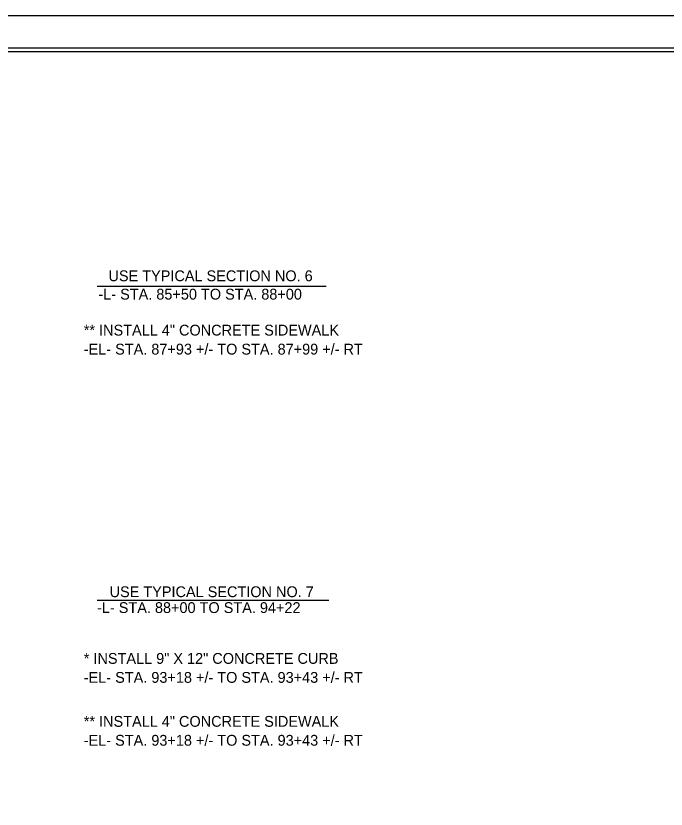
# Model space of a CAD drawing. Extents: x 1022283 to 1026986, y 174822 to 180471.
# Drawn here: x 1024733 to 1025859, y 176197 to 177572 of the extents above; entities that cross this region are included whole.
import ezdxf

# ---------------------------------------------------------------- set-up
doc = ezdxf.new("R2010")
doc.units = 0
for name, color, linetype in [('Prop Dimension', 7, 'Continuous'), ('Sheet Cutting Line CELL', 7, 'Continuous'), ('Sheet Plot Border Inside CELL', 7, 'Continuous'), ('Sheet Plot Border Outside CELL', 7, 'Continuous'), ('Sheet Typical CELL', 7, 'Continuous'), ('Typical Text Label CELL', 7, 'Continuous')]:
    doc.layers.add(name, color=color, linetype=linetype)

msp = doc.modelspace()

# ---------------------------------------------------------------- linework, layer by layer
at = {"layer": 'Sheet Cutting Line CELL'}
msp.add_line((1026493.2, 177572.5), (1022283.2, 177572.5), dxfattribs=at)
at = {"layer": 'Sheet Plot Border Inside CELL'}
msp.add_lwpolyline([(1026482, 177516.3), (1022315.7, 177516.3), (1022315.7, 174878.6), (1026482, 174878.6)], close=True, dxfattribs=at)
at = {"layer": 'Sheet Plot Border Outside CELL'}
msp.add_lwpolyline([(1026493.2, 177572.5), (1022283.2, 177572.5), (1022283.2, 174822.5), (1026493.2, 174822.5)], close=True, dxfattribs=at)
at = {"layer": 'Sheet Typical CELL'}
msp.add_lwpolyline([(1026450.7, 177510), (1022700.7, 177510), (1022700.7, 174885), (1026450.7, 174885)], close=True, dxfattribs=at)
at = {"layer": 'Typical Text Label CELL'}
for p, q in [((1024873.5, 177104), (1025270.1, 177104)), ((1024873.5, 176559.4), (1025275, 176559.4))]:
    msp.add_line(p, q, dxfattribs=at)

# ---------------------------------------------------------------- texts
at = {"layer": 'Prop Dimension'}
for s, p in [('-L- STA. 85+50 TO STA. 88+00', (1024875.6, 177080.7)), ('** INSTALL 4" CONCRETE SIDEWALK ', (1024850.2, 177018.3)), ('-EL- STA. 87+93 +/- TO STA. 87+99 +/- RT', (1024850.2, 176985.4)), ('-L- STA. 88+00 TO STA. 94+22', (1024873.2, 176537.4)), ('* INSTALL 9" X 12" CONCRETE CURB ', (1024850.2, 176449.3)), ('-EL- STA. 93+18 +/- TO STA. 93+43 +/- RT', (1024850.2, 176416.4)), ('** INSTALL 4" CONCRETE SIDEWALK ', (1024850.2, 176340.2)), ('-EL- STA. 93+18 +/- TO STA. 93+43 +/- RT', (1024850.2, 176307.4))]:
    msp.add_text(s, height=18.75, dxfattribs=at).set_placement(p)
at = {"layer": 'Typical Text Label CELL'}
for s, p in [('USE TYPICAL SECTION NO. 6', (1024893, 177112.5)), ('USE TYPICAL SECTION NO. 7', (1024894.9, 176564.9))]:
    msp.add_text(s, height=18.75, dxfattribs=at).set_placement(p)

doc.saveas('drawing.dxf')
